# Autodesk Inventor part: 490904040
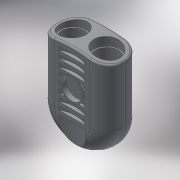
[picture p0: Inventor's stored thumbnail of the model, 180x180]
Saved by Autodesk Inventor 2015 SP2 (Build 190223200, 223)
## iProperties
Created: 2017-07
Part Number: 490904040
Material: Generic
Description: PLASSON 180° ELBOW 40
Document SubType Name: Modeling
Designer: Кирилл
Density: 1 g/cm^3
Appearance: Default
Author: Кирилл
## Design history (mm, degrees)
derived "490904.ipt"
feature "Solid1::490904.ipt"
tag "TaggingFeature1"
body "Solid1"
other parameters: "d0" = 106, "d1" = 123, "d2" = 24.6, "d3" = 10.6, "d4" = 98.4, "d5" = 63.6, "d6" = 53, "d7" = 0, "d8" = 36.9, "d9" = 36.9, "d10" = 23.85, "d11" = 2.65, "d12" = -24.6, "d13" = 21.2, "d14" = 42.4, "d15" = 36.9, "d16" = 0, "d17" = -4.92, "d18" = 4.92, "d19" = 0, "d22" = 9.84, "d23" = 37.1, "d24" = 73.8, "d26" = 0, "d27" = 31.8, "d28" = 6.625, "d29" = 0, "d30" = 0.53, "d31" = 0, "d34" = 53, "d35" = 26.5, "d36" = 48, "d37" = 0, "d38" = 44, "d39" = 44, "d40" = 12, "d41" = 0, "d42" = 36, "d43" = 180 deg, "d46" = 14, "d47" = 0, "d48" = 4, "d49" = 4.8, "d50" = 8, "d51" = 0, "d52" = 123, "d53" = 116.85, "L_" = 53, "L_1" = 48, "H_" = 123, "B_" = 106, "d_2" = 12
